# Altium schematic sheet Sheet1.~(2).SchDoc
size A4
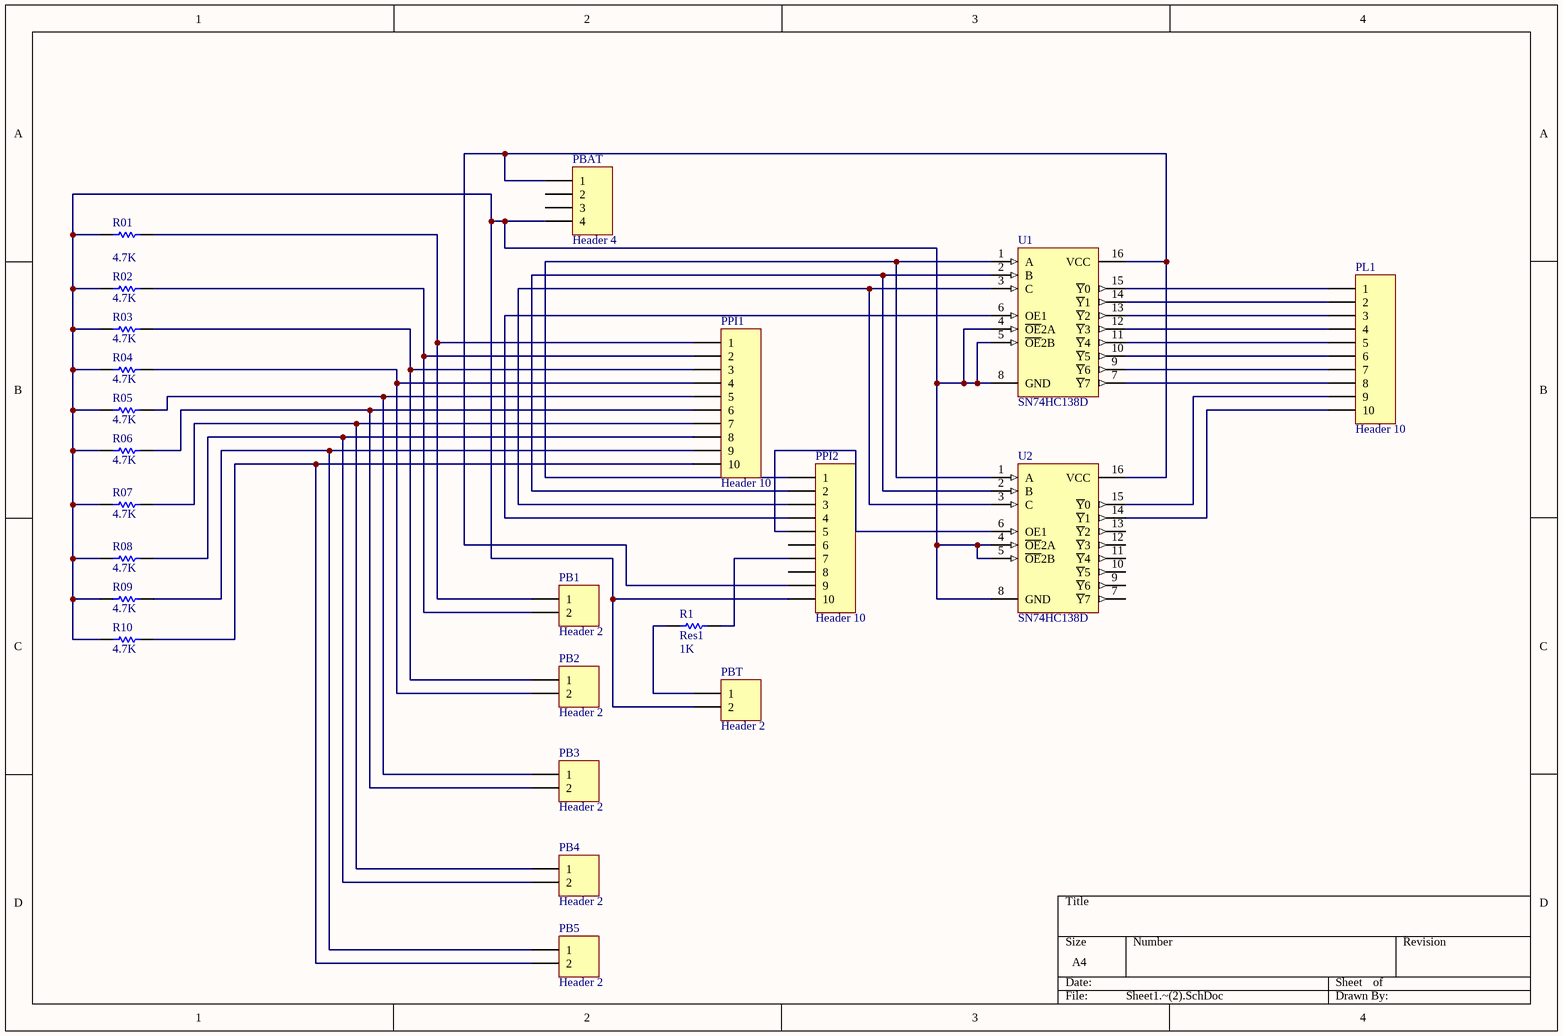
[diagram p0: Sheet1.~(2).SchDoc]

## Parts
PB1  Header 2  [HDR1X2]
PB2  Header 2  [HDR1X2]
PB3  Header 2  [HDR1X2]
PB4  Header 2  [HDR1X2]
PB5  Header 2  [HDR1X2]
PBAT  Header 4  [HDR1X4]
PBT  Header 2  [HDR1X2]
PL1  Header 10  [HDR1X10]
PPI1  Header 10  [HDR1X10]
PPI2  Header 10  [HDR1X10]
R1  Res1  value 1K  [AXIAL-0.3]
R01  value 4.7K  [AXIAL-0.3]  (hidden comment: Res1)
R02  value 4.7K  [AXIAL-0.3]  (hidden comment: Res1)
R03  value 4.7K  [AXIAL-0.3]  (hidden comment: Res1)
R04  value 4.7K  [AXIAL-0.3]  (hidden comment: Res1)
R05  value 4.7K  [AXIAL-0.3]  (hidden comment: Res1)
R06  value 4.7K  [AXIAL-0.3]  (hidden comment: Res1)
R07  value 4.7K  [AXIAL-0.3]  (hidden comment: Res1)
R08  value 4.7K  [AXIAL-0.3]  (hidden comment: Res1)
R09  value 4.7K  [AXIAL-0.3]  (hidden comment: Res1)
R10  value 4.7K  [AXIAL-0.3]  (hidden comment: Res1)
U1  SN74HC138D  [D016_N]
U2  SN74HC138D  [D016_N]

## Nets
NetPB1_1: PB1.1 PPI1.1 R01.2
NetPB1_2: PB1.2 PPI1.2 R02.2
NetPB2_1: PB2.1 PPI1.3 R03.2
NetPB2_2: PB2.2 PPI1.4 R04.2
NetPB3_1: PB3.1 PPI1.5 R05.2
NetPB3_2: PB3.2 PPI1.6 R06.2
NetPB4_1: PB4.1 PPI1.7 R07.2
NetPB4_2: PB4.2 PPI1.8 R08.2
NetPB5_1: PB5.1 PPI1.9 R09.2
NetPB5_2: PB5.2 PPI1.10 R10.2
NetPBAT_1: PBAT.1 PPI2.9 U1.16(VCC) U2.16(VCC)
NetPBAT_4: PBAT.4 PBT.2 PPI2.10 R01.1 R02.1 R03.1 R04.1 R05.1 R06.1 R07.1 R08.1 R09.1 R10.1 U1.4(~{OE}2A) U1.5(~{OE}2B) U1.8(GND) U2.4(~{OE}2A) U2.5(~{OE}2B) U2.8(GND)
NetPBT_1: PBT.1 R1.1
NetPL1_1: PL1.1 U1.15(~{Y}0)
NetPL1_2: PL1.2 U1.14(~{Y}1)
NetPL1_3: PL1.3 U1.13(~{Y}2)
NetPL1_4: PL1.4 U1.12(~{Y}3)
NetPL1_5: PL1.5 U1.11(~{Y}4)
NetPL1_6: PL1.6 U1.10(~{Y}5)
NetPL1_7: PL1.7 U1.9(~{Y}6)
NetPL1_8: PL1.8 U1.7(~{Y}7)
NetPL1_9: PL1.9 U2.15(~{Y}0)
NetPL1_10: PL1.10 U2.14(~{Y}1)
NetPPI2_1: PPI2.1 U1.1(A) U2.1(A)
NetPPI2_2: PPI2.2 U1.2(B) U2.2(B)
NetPPI2_3: PPI2.3 U1.3(C) U2.3(C)
NetPPI2_4: PPI2.4 U1.6(OE1)
NetPPI2_5: PPI2.5 U2.6(OE1)
NetPPI2_7: PPI2.7 R1.2

Not connected (* = marked no-connect by the designer): PBAT 2 3; PPI2 6 8; U2 7(~{Y}7) 9(~{Y}6) 10(~{Y}5) 11(~{Y}4) 12(~{Y}3) 13(~{Y}2)

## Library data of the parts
PB1-PB5 PBT = Header 2: Header, 2-Pin
PBAT = Header 4: Header, 4-Pin
PL1 PPI1 PPI2 = Header 10: Header, 10-Pin
R1 R01 R02 R03 R04 R05 R06 R07 R08 R09 R10 = Res1: Resistor
U1 U2 = SN74HC138D: 3-Line to 8-Line Decoder / Demultiplexer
